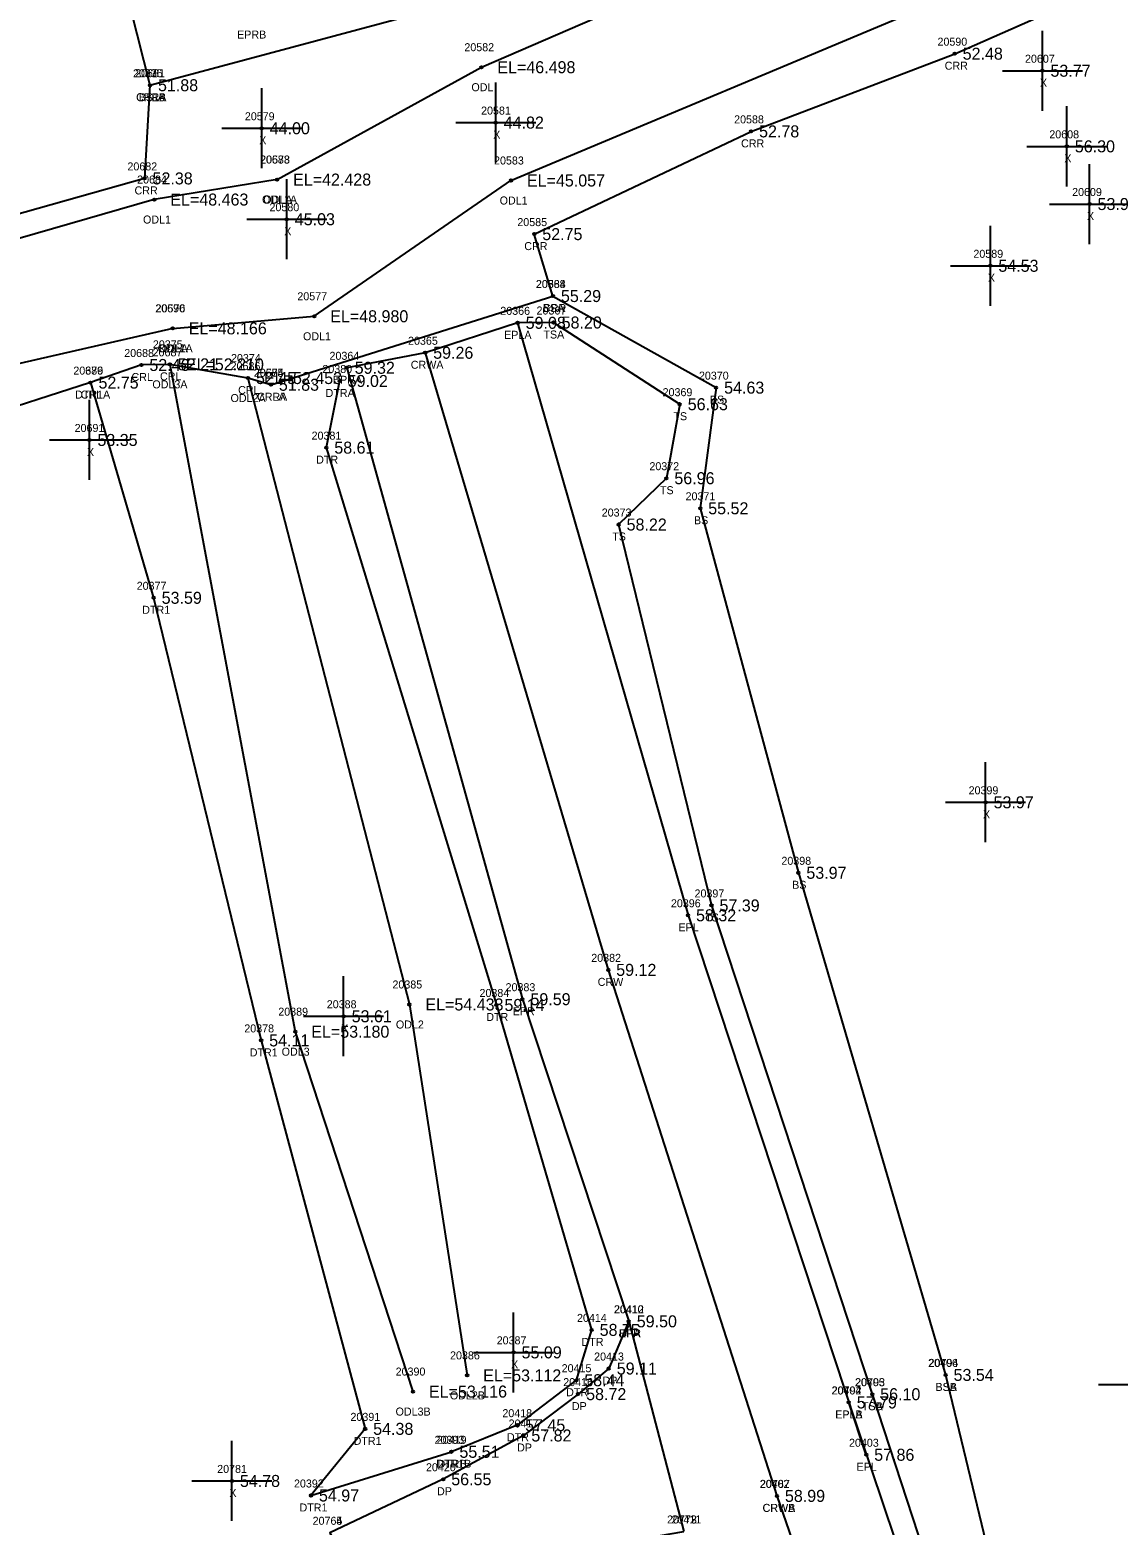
# Model space of a CAD drawing. Extents: x 2396547 to 2397655, y 770185 to 772649.
# Drawn here: x 2397011.4 to 2397147.4, y 771213.4 to 771400.3 of the extents above; entities that cross this region are included whole.
import ezdxf

# ---------------------------------------------------------------- set-up
doc = ezdxf.new("R2010")
doc.units = 0
for name, color, linetype in [('RD_DTM_BkLn1', 7, 'Continuous'), ('RD_DTM_BkLn2', 7, 'Continuous'), ('RD_DTM_BkLn_txCode', 7, 'Continuous'), ('RD_EX_Driveway', 7, 'Continuous'), ('RD_EX_Driveway_txCode', 7, 'Continuous'), ('RD_EX_H2O', 7, 'Continuous'), ('RD_EX_H2O_txCode', 7, 'Continuous'), ('RD_EX_Misc', 7, 'Continuous'), ('RD_EX_Misc_txCode', 7, 'Continuous'), ('RD_EX_Road', 7, 'Continuous'), ('RD_EX_Road_txCode', 7, 'Continuous'), ('RD_EX_TX_Driveway_ELEV', 7, 'Continuous'), ('RD_EX_TX_H2O_ELEV', 7, 'Continuous'), ('RD_EX_TX_Misc_ELEV', 7, 'Continuous'), ('RD_EX_TX_Road_ELEV', 7, 'Continuous'), ('RD_HC_Survey_ELEV', 7, 'Continuous'), ('RD_HC_Survey_txCode', 7, 'Continuous'), ('RD_SMD_Locator', 7, 'Continuous')]:
    doc.layers.add(name, color=color, linetype=linetype)

msp = doc.modelspace()

# ---------------------------------------------------------------- linework, layer by layer
at = {"layer": 'RD_DTM_BkLn1'}
for points in [[(2397060.81, 771359.95), (2397083.69, 771282.82), (2397104.78, 771217.07)], [(2397104.78, 771217.07), (2397119.02, 771175.87), (2397143.13, 771113.88), (2397170.45, 771052.64), (2397197.01, 770999.9), (2397235.12, 770930.63), (2397270.14, 770871.5)]]:
    msp.add_lwpolyline(points, dxfattribs=at)
at = {"layer": 'RD_DTM_BkLn2'}
for points in [[(2396921.95, 771810.18), (2396927.42, 771791.88), (2396939.93, 771742.16), (2396976.22, 771602.97), (2396999, 771501.35), (2397026.41, 771393.39)], [(2397076.78, 771367.04), (2397097.18, 771355.59), (2397095.19, 771340.51), (2397107.46, 771294.95), (2397125.86, 771232.19), (2397125.86, 771232.19), (2397138.17, 771181.02), (2397159.24, 771120.76), (2397175.38, 771088.12), (2397179.45, 771097.49), (2397196.45, 771092.84), (2397253.33, 771096.54)], [(2397076.87, 771363.73), (2397072.37, 771363.69), (2397060.81, 771359.95), (2397051, 771358.07)], [(2397076.87, 771363.73), (2397092.63, 771353.52), (2397090.96, 771344.27), (2397084.99, 771338.48), (2397096.6, 771290.87), (2397116.69, 771229.78), (2397116.69, 771229.78), (2397133.23, 771179.22), (2397155.87, 771119.34), (2397173.3, 771081.82), (2397181.13, 771084.07), (2397253.33, 771087)]]:
    msp.add_lwpolyline(points, dxfattribs=at)
at = {"layer": 'RD_EX_Driveway'}
msp.add_lwpolyline([(2397086.26, 771238.89), (2397083.76, 771232.99), (2397079.93, 771229.79), (2397073.08, 771224.62), (2397063.07, 771219.15), (2397048.88, 771212.46), (2397056.23, 771199.84), (2397070.51, 771208.74), (2397093.16, 771212.62)], dxfattribs=at)
at = {"layer": 'RD_EX_H2O'}
for points in [[(2397026.41, 771393.39), (2397070.16, 771405.14), (2397085.18, 771412.94), (2397115.64, 771424.52), (2397174.69, 771450.34), (2397230.25, 771466.48), (2397283.24, 771491.48), (2397342.91, 771519.42), (2397408.89, 771536.24), (2397447.46, 771546.47), (2397469.5, 771549.6), (2397497.19, 771541.27), (2397541.1, 771500.79)], [(2397042.3, 771381.6), (2397067.83, 771395.64), (2397118.36, 771417.53), (2397176.74, 771444.94), (2397209.62, 771454.54), (2397231.6, 771461.44), (2397284.94, 771486.86), (2397344.87, 771514.98), (2397410.89, 771531.68), (2397447.35, 771543.38), (2397470.51, 771546.83), (2397496.21, 771538.83), (2397538.93, 771498.41)], [(2397029.25, 771363), (2397046.94, 771364.51), (2397071.53, 771381.48), (2397124.8, 771403.82), (2397183.53, 771425.21), (2397238.71, 771441.76), (2397294.15, 771464.26), (2397352.71, 771489.51), (2397415.81, 771518.52), (2397439.88, 771522.42), (2397486.58, 771521.99), (2397528.15, 771484.04)], [(2397041.52, 771355.95), (2397076.78, 771367.04), (2397074.45, 771374.78), (2397101.55, 771387.62), (2397127, 771397.33), (2397184.13, 771422.52), (2397239.58, 771440.33), (2397295.12, 771461.42), (2397353.86, 771487.36), (2397417.93, 771512.91), (2397437.51, 771516.93), (2397483.94, 771516.4), (2397526.36, 771480.62)], [(2397026.41, 771393.39), (2397025.73, 771381.74), (2396981.24, 771369.21), (2396933.35, 771351.16), (2396867.1, 771327.21), (2396805.16, 771301.5), (2396726.77, 771268.25), (2396662.72, 771245.88), (2396570.19, 771208.11)], [(2397042.3, 771381.6), (2397026.95, 771379.1), (2396982.27, 771366.23), (2396935.45, 771345.14), (2396869.6, 771319.67), (2396806.56, 771295.91), (2396727.11, 771265.36), (2396664.85, 771241.65), (2396575.64, 771198.56)], [(2397029.25, 771363), (2396987.12, 771353.36), (2396940.53, 771333.19), (2396876.37, 771307.51), (2396813.23, 771283.31), (2396732.14, 771250.38), (2396668.87, 771226.62), (2396581.1, 771189.01)], [(2397041.52, 771355.95), (2397038.66, 771356.79), (2397028.89, 771358.5), (2397025.33, 771358.42), (2397018.97, 771356.22), (2396990.02, 771346.89), (2396942.55, 771327.39), (2396877.94, 771304.58), (2396814.23, 771281.47), (2396733.01, 771246.09), (2396670.48, 771223.24), (2396582.44, 771186.21)], [(2397028.89, 771358.5), (2397044.57, 771275.09), (2397059.28, 771230.11)], [(2397018.97, 771356.22), (2397026.87, 771329.32), (2397040.31, 771274), (2397053.31, 771225.45), (2397046.53, 771217.12), (2397064.09, 771222.58)], [(2397038.66, 771356.79), (2397058.84, 771278.49), (2397066.06, 771232.13)], [(2397050.12, 771356.42), (2397048.45, 771348.09), (2397069.72, 771278.43), (2397081.62, 771237.82), (2397079.7, 771231.53), (2397072.3, 771225.91), (2397064.09, 771222.58)]]:
    msp.add_lwpolyline(points, dxfattribs=at)
at = {"layer": 'RD_EX_Misc'}
for p, q in [((2397137.97, 771390.2), (2397137.97, 771400.2)), ((2397132.97, 771395.2), (2397142.97, 771395.2)), ((2397040.38, 771383.01), (2397040.38, 771393.01)), ((2397069.63, 771383.72), (2397069.63, 771393.72)), ((2397141.02, 771380.75), (2397141.02, 771390.75)), ((2397035.38, 771388.01), (2397045.38, 771388.01)), ((2397064.63, 771388.72), (2397074.63, 771388.72)), ((2397136.02, 771385.75), (2397146.02, 771385.75)), ((2397143.86, 771373.54), (2397143.86, 771383.54)), ((2397043.51, 771371.64), (2397043.51, 771381.64)), ((2397138.86, 771378.54), (2397148.86, 771378.54)), ((2397038.51, 771376.64), (2397048.51, 771376.64)), ((2397131.46, 771365.82), (2397131.46, 771375.82)), ((2397126.46, 771370.82), (2397136.46, 771370.82)), ((2397018.84, 771344.05), (2397018.84, 771354.05)), ((2397013.84, 771349.05), (2397023.84, 771349.05)), ((2397130.86, 771298.76), (2397130.86, 771308.76)), ((2397125.86, 771303.76), (2397135.86, 771303.76)), ((2397050.62, 771272.02), (2397050.62, 771282.02)), ((2397045.62, 771277.02), (2397055.62, 771277.02)), ((2397071.86, 771230.01), (2397071.86, 771240.01)), ((2397066.86, 771235.01), (2397076.86, 771235.01)), ((2397144.99, 771230.99), (2397154.99, 771230.99)), ((2397036.65, 771213.94), (2397036.65, 771223.94)), ((2397031.65, 771218.94), (2397041.65, 771218.94))]:
    msp.add_line(p, q, dxfattribs=at)
at = {"layer": 'RD_EX_Road'}
for points in [[(2397072.37, 771363.69), (2397093.67, 771289.64), (2397115.94, 771222.21), (2397113.76, 771228.75)], [(2397051, 771358.07), (2397072.97, 771279.15), (2397086.26, 771238.89), (2397093.16, 771212.62)], [(2397113.76, 771228.75), (2397130.87, 771177.98), (2397154.19, 771118.49), (2397170.38, 771081.25), (2397178.53, 771063.49), (2397207.96, 771004.56), (2397238.54, 770949.11), (2397245.72, 770936.59), (2397280.76, 770876.73)]]:
    msp.add_lwpolyline(points, dxfattribs=at)
at = {"layer": 'RD_SMD_Locator'}
for centre in [(2397127, 771397.33), (2397067.83, 771395.64), (2397137.97, 771395.2), (2397026.41, 771393.39), (2397026.41, 771393.39), (2397026.41, 771393.39), (2397040.38, 771388.01), (2397069.63, 771388.72), (2397101.55, 771387.62), (2397141.02, 771385.75), (2397025.73, 771381.74), (2397042.3, 771381.6), (2397042.3, 771381.6), (2397071.53, 771381.48), (2397026.95, 771379.1), (2397143.86, 771378.54), (2397043.51, 771376.64), (2397074.45, 771374.78), (2397131.46, 771370.82), (2397076.78, 771367.04), (2397076.78, 771367.04), (2397029.25, 771363), (2397029.25, 771363), (2397046.94, 771364.51), (2397072.37, 771363.69), (2397076.87, 771363.73), (2397060.81, 771359.95), (2397025.33, 771358.42), (2397028.89, 771358.5), (2397028.89, 771358.5), (2397051, 771358.07), (2397018.97, 771356.22), (2397018.97, 771356.22), (2397038.66, 771356.79), (2397038.66, 771356.79), (2397041.52, 771355.95), (2397041.52, 771355.95), (2397050.12, 771356.42), (2397097.18, 771355.59), (2397092.63, 771353.52), (2397018.84, 771349.05), (2397048.45, 771348.09), (2397090.96, 771344.27), (2397095.19, 771340.51), (2397084.99, 771338.48), (2397026.87, 771329.32), (2397130.86, 771303.76), (2397107.46, 771294.95), (2397096.6, 771290.87), (2397093.67, 771289.64), (2397083.69, 771282.82), (2397072.97, 771279.15), (2397050.62, 771277.02), (2397058.84, 771278.49), (2397069.72, 771278.43), (2397044.57, 771275.09), (2397040.31, 771274), (2397081.62, 771237.82), (2397086.26, 771238.89), (2397086.26, 771238.89), (2397071.86, 771235.01), (2397066.06, 771232.13), (2397083.76, 771232.99), (2397125.86, 771232.19), (2397125.86, 771232.19), (2397079.7, 771231.53), (2397059.28, 771230.11), (2397079.93, 771229.79), (2397113.76, 771228.75), (2397113.76, 771228.75), (2397116.69, 771229.78), (2397116.69, 771229.78), (2397053.31, 771225.45), (2397072.3, 771225.91), (2397073.08, 771224.62), (2397064.09, 771222.58), (2397064.09, 771222.58), (2397115.94, 771222.21), (2397063.07, 771219.15), (2397036.65, 771218.94), (2397046.53, 771217.12), (2397104.78, 771217.07), (2397104.78, 771217.07)]:
    msp.add_circle(centre, 0.15, dxfattribs=at)

# ---------------------------------------------------------------- texts
at = {"layer": 'RD_DTM_BkLn_txCode'}
for s, p in [('20335', (2397024.29, 771394.39)), ('BS1B', (2397024.99, 771391.39)), ('20368', (2397074.64, 771368.04)), ('20367', (2397074.73, 771364.73)), ('BSA', (2397075.51, 771365.04)), ('TSA', (2397075.59, 771361.73)), ('20370', (2397095.03, 771356.59)), ('20369', (2397090.49, 771354.52)), ('BS', (2397096.4, 771353.59)), ('TS', (2397091.84, 771351.52)), ('20372', (2397088.84, 771345.27)), ('TS', (2397090.16, 771342.27)), ('20371', (2397093.36, 771341.51)), ('20373', (2397082.88, 771339.48)), ('BS', (2397094.41, 771338.51)), ('TS', (2397084.2, 771336.48)), ('20398', (2397105.34, 771295.95)), ('BS', (2397106.68, 771292.95)), ('20397', (2397094.48, 771291.87)), ('TS', (2397095.81, 771288.87)), ('20406', (2397123.68, 771233.19)), ('20794', (2397123.74, 771233.19)), ('20405', (2397114.53, 771230.78)), ('20793', (2397114.57, 771230.78)), ('BSA', (2397124.59, 771230.19)), ('BSB', (2397124.61, 771230.19)), ('TSA', (2397115.4, 771227.78)), ('TSB', (2397115.42, 771227.78))]:
    msp.add_text(s, height=1, dxfattribs=at).set_placement(p)
at = {"layer": 'RD_EX_Driveway_txCode'}
for s, p in [('20412', (2397084.43, 771239.89)), ('DPA', (2397085, 771236.89)), ('20413', (2397081.93, 771233.99)), ('20416', (2397078.07, 771230.79)), ('DP', (2397082.98, 771230.99)), ('DP', (2397079.15, 771227.79)), ('20417', (2397071.24, 771225.62)), ('DP', (2397072.3, 771222.62)), ('20420', (2397060.91, 771220.15)), ('DP', (2397062.29, 771217.15)), ('20764', (2397046.74, 771213.46)), ('20765', (2397046.74, 771213.46)), ('20772', (2397091.04, 771213.62))]:
    msp.add_text(s, height=1, dxfattribs=at).set_placement(p)
at = {"layer": 'RD_EX_H2O_txCode'}
for s, p in [('20582', (2397065.71, 771397.64)), ('20590', (2397124.85, 771398.33)), ('20575', (2397024.29, 771394.39)), ('20681', (2397024.55, 771394.39)), ('CRR', (2397125.75, 771395.33)), ('ODL', (2397066.59, 771392.64)), ('CRRA', (2397024.67, 771391.39)), ('CRLA', (2397024.69, 771391.39)), ('20588', (2397099.43, 771388.62)), ('CRR', (2397100.3, 771385.62)), ('20682', (2397023.59, 771382.74)), ('20683', (2397040.16, 771383.6)), ('20578', (2397040.19, 771383.6)), ('20583', (2397069.42, 771383.48)), ('20684', (2397024.8, 771381.1)), ('CRR', (2397024.48, 771379.74)), ('ODL1A', (2397040.41, 771378.6)), ('ODLA', (2397040.57, 771378.6)), ('ODL1', (2397070.12, 771378.48)), ('ODL1', (2397025.54, 771376.1)), ('20585', (2397072.33, 771375.78)), ('CRR', (2397073.2, 771372.78)), ('20584', (2397074.66, 771368.04)), ('20577', (2397044.83, 771366.51)), ('20690', (2397027.07, 771365)), ('20576', (2397027.11, 771365)), ('CRR', (2397075.53, 771365.04)), ('20375', (2397026.77, 771360.5)), ('ODL1', (2397045.54, 771361.51)), ('20688', (2397023.19, 771359.42)), ('20687', (2397026.74, 771359.5)), ('ODL1A', (2397027.36, 771360)), ('ODLA', (2397027.52, 771360)), ('20374', (2397036.54, 771358.79)), ('20376', (2397016.83, 771357.22)), ('20689', (2397016.83, 771357.22)), ('CRL', (2397024.1, 771356.42)), ('CRL', (2397027.66, 771356.5)), ('20686', (2397036.49, 771357.79)), ('20685', (2397039.38, 771356.95)), ('20574', (2397039.4, 771356.95)), ('20380', (2397047.96, 771357.42)), ('ODL3A', (2397026.71, 771355.5)), ('CRL', (2397037.43, 771354.79)), ('DTR1A', (2397017.05, 771354.22)), ('CRL', (2397017.75, 771354.22)), ('ODL2A', (2397036.48, 771353.79)), ('CRRA', (2397039.78, 771353.95)), ('CRLA', (2397039.8, 771353.95)), ('DTRA', (2397048.36, 771354.42)), ('20381', (2397046.61, 771349.09)), ('DTR', (2397047.18, 771346.09)), ('20377', (2397024.75, 771330.32)), ('DTR1', (2397025.44, 771327.32)), ('20385', (2397056.72, 771280.49)), ('20384', (2397067.6, 771279.43)), ('20389', (2397042.45, 771277.09)), ('DTR', (2397068.45, 771276.43)), ('20378', (2397038.2, 771275)), ('ODL2', (2397057.15, 771275.49)), ('DTR1', (2397038.88, 771272)), ('ODL3', (2397042.87, 771272.09)), ('20414', (2397079.79, 771238.82)), ('DTR', (2397080.36, 771235.82)), ('20386', (2397063.92, 771234.13)), ('20390', (2397057.12, 771232.11)), ('20415', (2397077.87, 771232.53)), ('DTR', (2397078.43, 771229.53)), ('ODL2B', (2397063.9, 771229.13)), ('20391', (2397051.47, 771226.45)), ('ODL3B', (2397057.11, 771227.11)), ('20418', (2397070.46, 771226.91)), ('DTR', (2397071.03, 771223.91)), ('DTR1', (2397051.87, 771223.45)), ('20393', (2397061.98, 771223.58)), ('20419', (2397062.26, 771223.58)), ('DTR1B', (2397062.19, 771220.58)), ('DTRB', (2397062.35, 771220.58)), ('20392', (2397044.41, 771218.12)), ('DTR1', (2397045.1, 771215.12))]:
    msp.add_text(s, height=1, dxfattribs=at).set_placement(p)
at = {"layer": 'RD_EX_Misc_txCode'}
for s, p in [('20607', (2397135.79, 771396.2)), ('X', (2397137.66, 771393.2)), ('20579', (2397038.27, 771389.01)), ('20581', (2397067.8, 771389.72)), ('X', (2397069.32, 771386.72)), ('20608', (2397138.83, 771386.75)), ('X', (2397040.07, 771386.01)), ('X', (2397140.7, 771383.75)), ('20609', (2397141.68, 771379.54)), ('20580', (2397041.35, 771377.64)), ('X', (2397143.54, 771376.54)), ('X', (2397043.19, 771374.64)), ('20589', (2397129.34, 771371.82)), ('X', (2397131.15, 771368.82)), ('20691', (2397016.99, 771350.05)), ('X', (2397018.53, 771347.05)), ('20399', (2397128.74, 771304.76)), ('X', (2397130.54, 771301.76)), ('20388', (2397048.51, 771278.02)), ('X', (2397050.31, 771275.02)), ('20387', (2397069.75, 771236.01)), ('X', (2397071.55, 771233.01)), ('20781', (2397034.81, 771219.94)), ('X', (2397036.33, 771216.94))]:
    msp.add_text(s, height=1, dxfattribs=at).set_placement(p)
at = {"layer": 'RD_EX_Road_txCode'}
for s, p in [('EPRB', (2397037.3, 771399.22)), ('20366', (2397070.2, 771364.69)), ('EPLA', (2397070.68, 771361.69)), ('20364', (2397048.85, 771359.07)), ('EPRA', (2397049.28, 771356.07)), ('20396', (2397091.53, 771290.64)), ('EPL', (2397092.47, 771287.64)), ('20383', (2397070.86, 771280.15)), ('EPR', (2397071.75, 771277.15)), ('20410', (2397084.39, 771239.89)), ('EPR', (2397085.04, 771236.89)), ('20404', (2397111.6, 771229.75)), ('20792', (2397111.64, 771229.75)), ('EPLA', (2397112.06, 771226.75)), ('EPLB', (2397112.08, 771226.75)), ('20403', (2397113.79, 771223.21)), ('EPL', (2397114.74, 771220.21)), ('20773', (2397091.04, 771213.62)), ('20411', (2397091.6, 771213.62))]:
    msp.add_text(s, height=1, dxfattribs=at).set_placement(p)
at = {"layer": 'RD_EX_TX_Driveway_ELEV'}
for s, p in [('59.50', (2397087.26, 771238.14)), ('59.11', (2397084.76, 771232.24)), ('58.72', (2397080.93, 771229.04)), ('57.82', (2397074.08, 771223.87)), ('56.55', (2397064.07, 771218.4))]:
    msp.add_text(s, height=1.5, dxfattribs=at).set_placement(p)
at = {"layer": 'RD_EX_TX_H2O_ELEV'}
for s, p in [('52.48', (2397128, 771396.58)), ('EL=46.498', (2397069.83, 771394.89)), ('51.88', (2397027.41, 771392.64)), ('51.88', (2397027.41, 771392.64)), ('52.78', (2397102.55, 771386.87)), ('52.38', (2397026.73, 771380.99)), ('EL=42.428', (2397044.3, 771380.85)), ('EL=42.428', (2397044.3, 771380.85)), ('EL=45.057', (2397073.53, 771380.73)), ('EL=48.463', (2397028.95, 771378.35)), ('52.75', (2397075.45, 771374.03)), ('55.29', (2397077.78, 771366.29)), ('EL=48.980', (2397048.94, 771363.76)), ('EL=48.166', (2397031.25, 771362.25)), ('EL=48.166', (2397031.25, 771362.25)), ('52.21', (2397029.89, 771357.75)), ('EL=52.210', (2397030.89, 771357.75)), ('52.46', (2397026.33, 771357.67)), ('52.45', (2397039.66, 771356.04)), ('EL=52.453', (2397040.66, 771356.04)), ('52.75', (2397019.97, 771355.47)), ('52.75', (2397019.97, 771355.47)), ('51.83', (2397042.52, 771355.2)), ('51.83', (2397042.52, 771355.2)), ('59.02', (2397051.12, 771355.67)), ('58.61', (2397049.45, 771347.34)), ('53.59', (2397027.87, 771328.57)), ('EL=54.433', (2397060.84, 771277.74)), ('59.14', (2397070.72, 771277.68)), ('EL=53.180', (2397046.57, 771274.34)), ('54.11', (2397041.31, 771273.25)), ('58.75', (2397082.62, 771237.07)), ('EL=53.112', (2397068.06, 771231.38)), ('58.44', (2397080.7, 771230.78)), ('EL=53.116', (2397061.28, 771229.36)), ('57.45', (2397073.3, 771225.16)), ('54.38', (2397054.31, 771224.7)), ('55.51', (2397065.09, 771221.83)), ('55.51', (2397065.09, 771221.83)), ('54.97', (2397047.53, 771216.37))]:
    msp.add_text(s, height=1.5, dxfattribs=at).set_placement(p)
at = {"layer": 'RD_EX_TX_Misc_ELEV'}
for s, p in [('53.77', (2397138.97, 771394.45)), ('51.88', (2397027.41, 771392.64)), ('44.82', (2397070.63, 771387.97)), ('44.00', (2397041.38, 771387.26)), ('56.30', (2397142.02, 771385)), ('53.96', (2397144.86, 771377.79)), ('45.03', (2397044.51, 771375.89)), ('54.53', (2397132.46, 771370.07)), ('55.29', (2397077.78, 771366.29)), ('58.20', (2397077.87, 771362.98)), ('54.63', (2397098.18, 771354.84)), ('56.63', (2397093.63, 771352.77)), ('53.35', (2397019.84, 771348.3)), ('56.96', (2397091.96, 771343.52)), ('55.52', (2397096.19, 771339.76)), ('58.22', (2397085.99, 771337.73)), ('53.97', (2397131.86, 771303.01)), ('53.97', (2397108.46, 771294.2)), ('57.39', (2397097.6, 771290.12)), ('53.61', (2397051.62, 771276.27)), ('55.09', (2397072.86, 771234.26)), ('53.54', (2397126.86, 771231.44)), ('53.54', (2397126.86, 771231.44)), ('56.10', (2397117.69, 771229.03)), ('56.10', (2397117.69, 771229.03)), ('54.78', (2397037.65, 771218.19))]:
    msp.add_text(s, height=1.5, dxfattribs=at).set_placement(p)
at = {"layer": 'RD_EX_TX_Road_ELEV'}
for s, p in [('59.08', (2397073.37, 771362.94)), ('59.32', (2397052, 771357.32)), ('58.32', (2397094.67, 771288.89)), ('59.59', (2397073.97, 771278.4)), ('59.50', (2397087.26, 771238.14)), ('57.79', (2397114.76, 771228)), ('57.79', (2397114.76, 771228)), ('57.86', (2397116.94, 771221.46))]:
    msp.add_text(s, height=1.5, dxfattribs=at).set_placement(p)
at = {"layer": 'RD_HC_Survey_ELEV'}
for s, p in [('59.26', (2397061.81, 771359.2)), ('59.12', (2397084.69, 771282.07)), ('58.99', (2397105.78, 771216.32)), ('58.99', (2397105.78, 771216.32))]:
    msp.add_text(s, height=1.5, dxfattribs=at).set_placement(p)
at = {"layer": 'RD_HC_Survey_txCode'}
for s, p in [('20365', (2397058.67, 771360.95)), ('CRWA', (2397059.01, 771357.95)), ('20382', (2397081.57, 771283.82)), ('CRW', (2397082.38, 771280.82)), ('20402', (2397102.63, 771218.07)), ('20787', (2397102.67, 771218.07)), ('CRWA', (2397102.98, 771215.07)), ('CRWB', (2397103, 771215.07))]:
    msp.add_text(s, height=1, dxfattribs=at).set_placement(p)

doc.saveas('drawing.dxf')
